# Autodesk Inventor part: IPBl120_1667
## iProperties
Company: CAD-Verlag
Shininess: 64.0
Length Units: 11269
Angle Units: 11279
Time Units: 11290
Mass Units: 11283
Length Display Precision: 3
Angle Display Precision: 2
Compacted: True
Part Number: IPBl120_1667
Document SubType Name: Modeling
Created: 2004-09
Material: Standard
Designer: Greiling
Manufacturer: Standard
Standards Organization: Custom
Density: 0.0
Volumn: 0.0
Area: 0.0
PropertySet Name: Model Information
Control State: 0
Master: False
Checked Out: False
Author: Jürgen Kronas
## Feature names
1. Extrusion1
